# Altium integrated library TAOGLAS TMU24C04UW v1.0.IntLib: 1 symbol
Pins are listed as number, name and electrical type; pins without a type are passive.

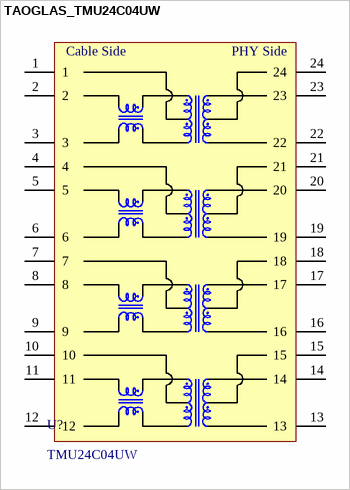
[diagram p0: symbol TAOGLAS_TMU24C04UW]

## TAOGLAS_TMU24C04UW
designator U?, comment TMU24C04UW
2.5G Base-T transformer Single Port and 24pin SMT; ComponentLibStatus: Created; MFG: Taoglas; Temp_High: +85C; Temp_Low: -40C
footprint TAOGLAS_TMU24C04UW (2.5G Base-T transformer Single Port and 24pin SMT)
pins: 1, 2, 3, 4, 5, 6, 7, 8, 9, 10, 11, 12, 13, 14, 15, 16, 17, 18, 19, 20, 21, 22, 23, 24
